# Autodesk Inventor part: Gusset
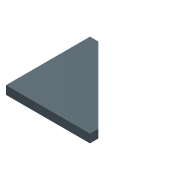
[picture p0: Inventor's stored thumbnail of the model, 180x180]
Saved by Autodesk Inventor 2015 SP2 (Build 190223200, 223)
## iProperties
Created: 2020-01
Part Number: Gusset
Material: 一般
Document SubType Name: Modeling
Designer: Kuan_Lun Hsu
Density: 1 g/cm^3
Appearance: 鉛
Author: Kuan_Lun Hsu
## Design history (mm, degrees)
sketch "草圖1"
  geometry: L1 (0, 0)-(0, 100); L2 (0, 100)-(10, 100); L3 (10, 100)-(100, 10); L4 (100, 10)-(100, 0); L5 (100, 0)-(0, 0)
  constraints: 10 end point, 3 perpendicular, 1 parallel, 1 vertical
  dimensions: "d0" = 10 distance of L1.end L2.end; "d1" = 100 distance of L1.start L1.end; "d2" = 100 distance of L4.end L1.start
extrude "擠出1" new body sketch "草圖1" stored distance "d3" = 10; taper "d4" = 0 deg
node "實體1"
